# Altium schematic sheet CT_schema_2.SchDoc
size 313 x 185 mm
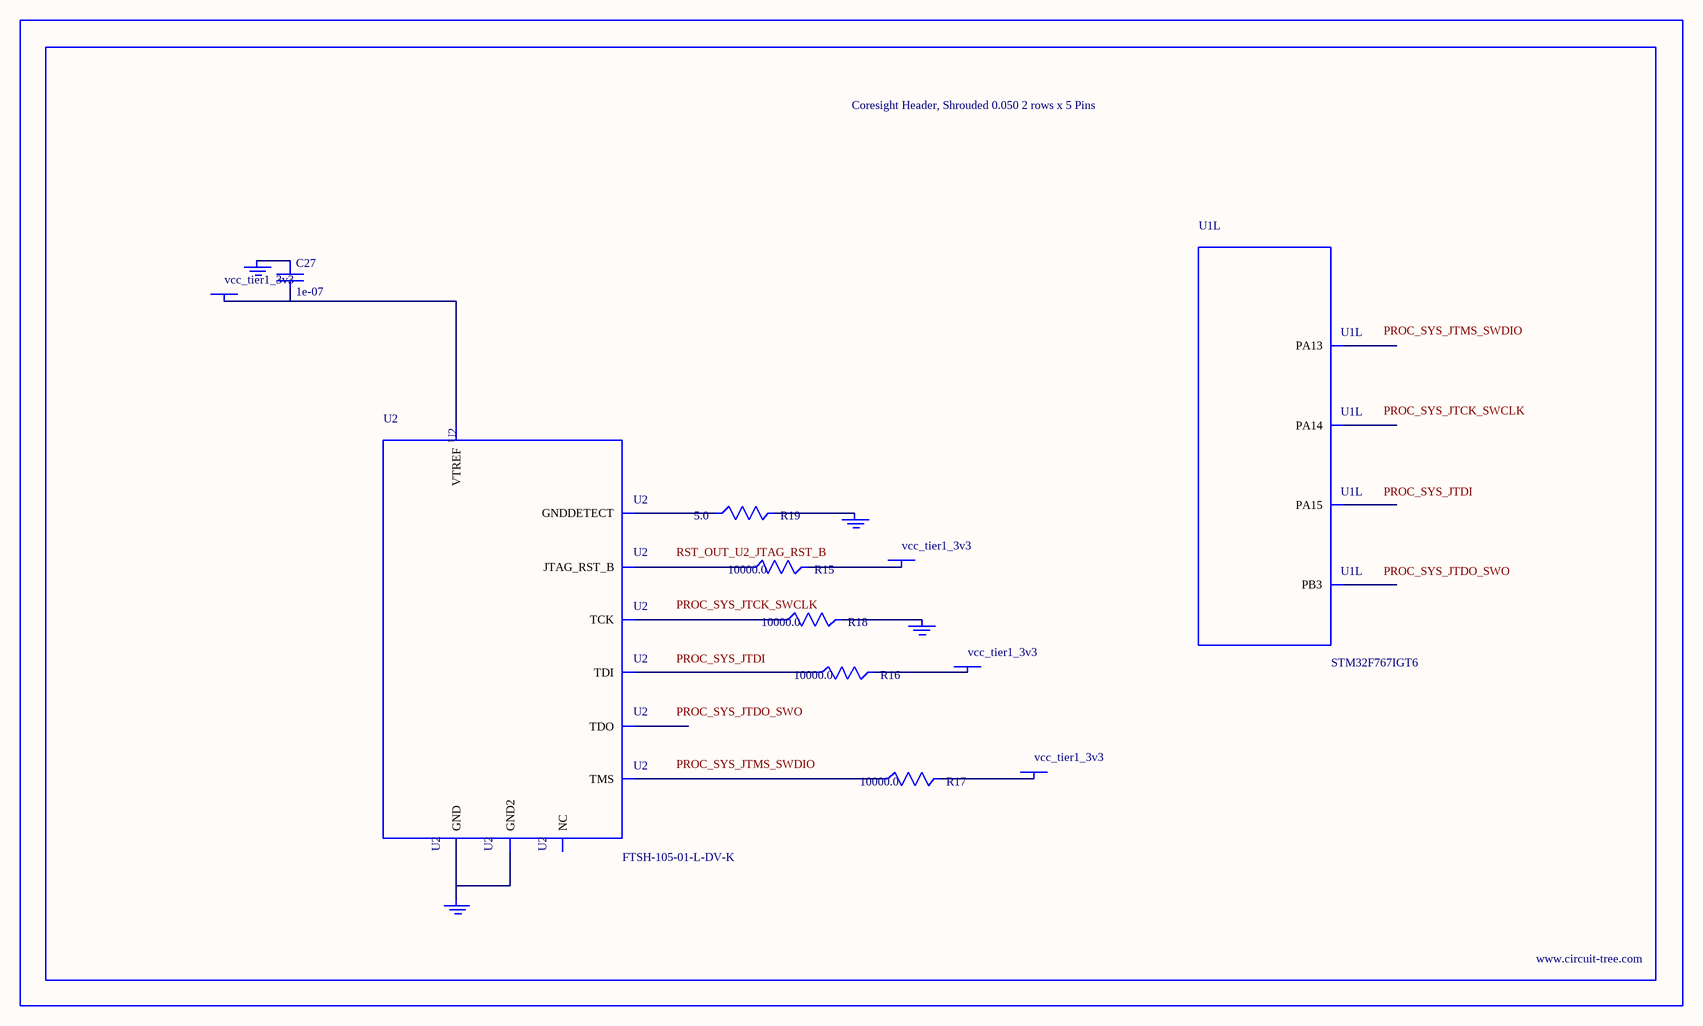
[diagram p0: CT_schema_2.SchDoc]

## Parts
BORDER1  (no value)
C27  1e-07  [C0402]
GND_INSTANCE_1_0  (no value)
GND_INSTANCE_1_1  (no value)
GND_INSTANCE_1_2  (no value)
GND_INSTANCE_1_3  (no value)
POWER_INSTANCE_1_0  vcc_tier1_3v3
POWER_INSTANCE_1_1  vcc_tier1_3v3
POWER_INSTANCE_1_2  vcc_tier1_3v3
POWER_INSTANCE_1_3  vcc_tier1_3v3
R15  10000.0  [R0603]
R16  10000.0  [R0603]
R17  10000.0  [R0603]
R18  10000.0  [R0603]
R19  5.0  [R0603]
U1  STM32F767IGT6  [LQFP176]  (part L of 13)
U2  FTSH-105-01-L-DV-K  [SAMTEC_FTSH-105-01-L-DV-K]

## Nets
NetC27_1: C27.1 GND_INSTANCE_1_0.0(GND)
NetC27_2: C27.2 POWER_INSTANCE_1_0.0(PWR) U2.1(VTREF)
NetGND_INSTANCE_1_1_0: GND_INSTANCE_1_1.0(GND) R18.2
NetGND_INSTANCE_1_2_0: GND_INSTANCE_1_2.0(GND) R19.2
NetGND_INSTANCE_1_3_0: GND_INSTANCE_1_3.0(GND) U2.3(GND) U2.5(GND2)
NetPOWER_INSTANCE_1_1_0: POWER_INSTANCE_1_1.0(PWR) R17.2
NetPOWER_INSTANCE_1_2_0: POWER_INSTANCE_1_2.0(PWR) R16.2
NetPOWER_INSTANCE_1_3_0: POWER_INSTANCE_1_3.0(PWR) R15.2
NetR15_1: R15.1 U2.10(JTAG_RST_B)
NetR16_1: R16.1 U2.8(TDI)
NetR17_1: R17.1 U2.2(TMS)
NetR18_1: R18.1 U2.4(TCK)
NetR19_1: R19.1 U2.9(GNDDETECT)

Not connected (* = marked no-connect by the designer): U1 124(PA13) 137(PA14) 138(PA15) 161(PB3); U2 6(TDO) 7(NC)

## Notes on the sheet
- Labels drawn without touching a wire or pin: PROC_SYS_JTCK_SWCLK, PROC_SYS_JTDI, PROC_SYS_JTDO_SWO, PROC_SYS_JTMS_SWDIO, RST_OUT_U2_JTAG_RST_B

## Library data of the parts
BORDER1 = BORDER_PAGE1
C27 = C0402C104K3RACTU
GND_INSTANCE_1_0-GND_INSTANCE_1_3 = GND
POWER_INSTANCE_1_0-POWER_INSTANCE_1_3 = PWR
R15-R18 = RC0603JR-0710KL
R19 = ERJ-3GEYJ5R1V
